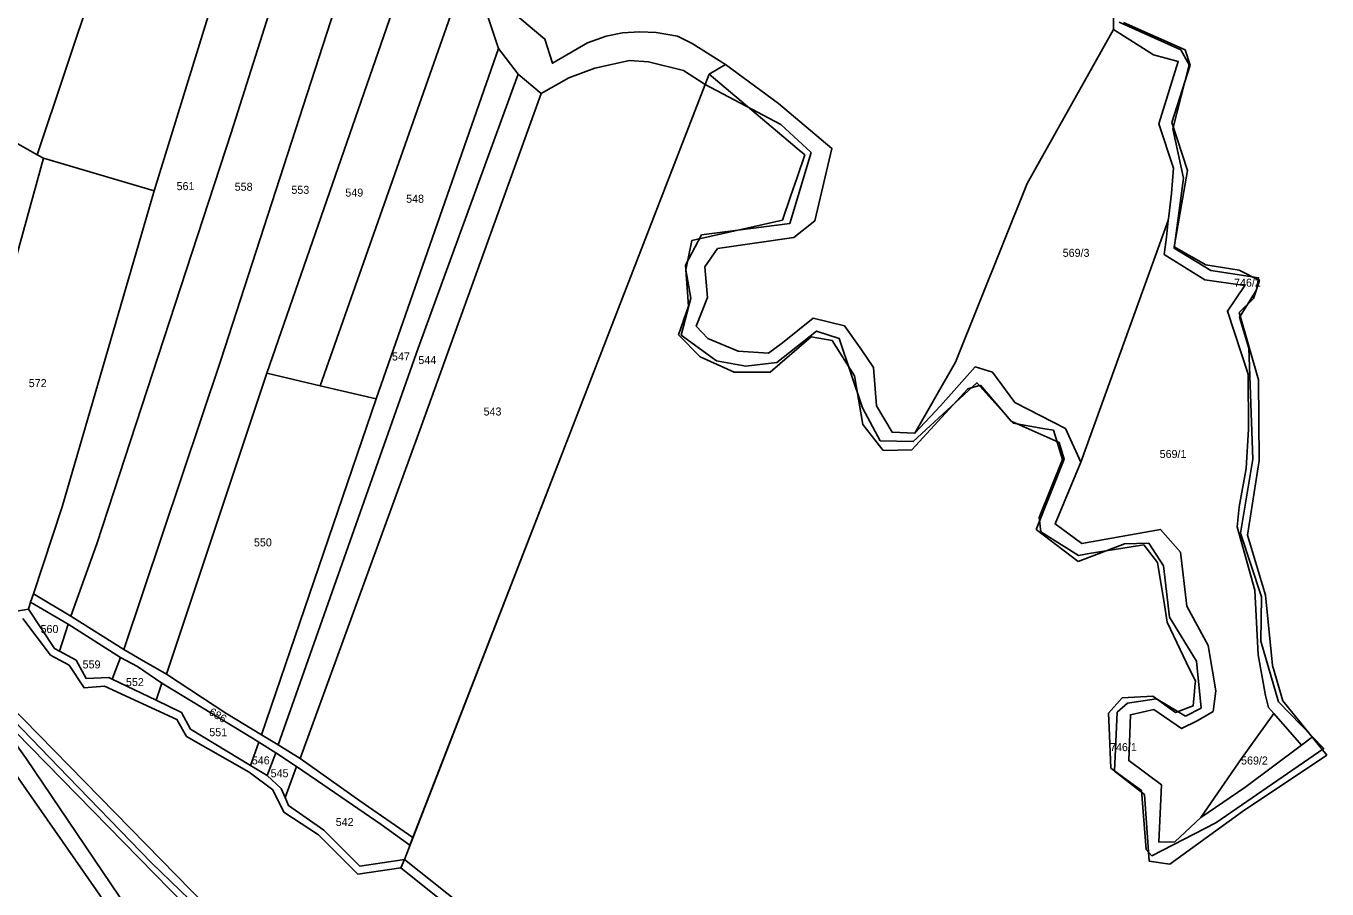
# Model space of a CAD drawing. Extents: x -629983 to -626385, y -1072828 to -1067897.
# Drawn here: x -627583.2 to -627095.5, y -1069313.4 to -1068989.9 of the extents above; entities that cross this region are included whole.
import ezdxf

# ---------------------------------------------------------------- set-up
doc = ezdxf.new("R2010")
doc.units = 0
for name, color, linetype in [('Katastrální hranice', 7, 'Continuous'), ('Parcela nároku', 7, 'Continuous'), ('Parcelní číslo', 7, 'Continuous'), ('Plocha PÚ', 7, 'Continuous'), ('Převzatý obvod_Vraclav', 7, 'Continuous'), ('voda', 7, 'Continuous'), ('Šetřený obvod', 7, 'Continuous')]:
    doc.layers.add(name, color=color, linetype=linetype)

msp = doc.modelspace()

# ---------------------------------------------------------------- linework, layer by layer
at = {"layer": 'Katastrální hranice'}
for p, q in [((-627171.7, -1068988.54), (-627148.6, -1068998.82)), ((-627148.6, -1068998.82), (-627146.76, -1069004.53)), ((-627146.76, -1069004.53), (-627153.59, -1069026.1)), ((-627328.55, -1069011.86), (-627300.22, -1069026.82)), ((-627288.82, -1069037.27), (-627300.22, -1069026.82)), ((-627153.59, -1069026.1), (-627147.78, -1069044.05)), ((-627296.85, -1069063.86), (-627288.82, -1069037.27)), ((-627152.7, -1069072.62), (-627147.78, -1069044.05)), ((-627329.97, -1069068.14), (-627296.85, -1069063.86)), ((-627335.89, -1069079.56), (-627329.97, -1069068.14)), ((-627152.7, -1069072.62), (-627140.88, -1069079.45)), ((-627334.78, -1069094.89), (-627335.89, -1069079.56)), ((-627140.88, -1069079.45), (-627128.35, -1069081.39)), ((-627120.7, -1069085.26), (-627128.35, -1069081.39)), ((-627120.7, -1069085.26), (-627122.95, -1069092.06)), ((-627122.95, -1069092.06), (-627128.35, -1069097.26)), ((-627338.55, -1069105.7), (-627334.78, -1069094.89)), ((-627128.35, -1069097.26), (-627121.12, -1069122.54)), ((-627330.5, -1069113.86), (-627338.55, -1069105.7)), ((-627288.86, -1069106.44), (-627304.24, -1069119.7)), ((-627281.01, -1069107.77), (-627288.86, -1069106.44)), ((-627281.01, -1069107.77), (-627272.57, -1069121)), ((-627317.66, -1069119.67), (-627330.5, -1069113.86)), ((-627304.24, -1069119.7), (-627317.66, -1069119.67)), ((-627269.42, -1069139.31), (-627272.57, -1069121)), ((-627251.09, -1069148.79), (-627230.1, -1069125.95)), ((-627225.31, -1069124.53), (-627230.1, -1069125.95)), ((-627213.79, -1069137.99), (-627225.31, -1069124.53)), ((-627121.12, -1069122.54), (-627120.91, -1069152.77)), ((-627261.88, -1069149), (-627269.42, -1069139.31)), ((-627195.86, -1069146.04), (-627213.79, -1069137.99)), ((-627195.86, -1069146.04), (-627194.03, -1069152.22)), ((-627251.09, -1069148.79), (-627261.88, -1069149)), ((-627204.42, -1069178.63), (-627194.03, -1069152.22)), ((-627120.91, -1069152.77), (-627125.19, -1069180.77)), ((-627188.78, -1069190.62), (-627204.42, -1069178.63)), ((-627125.19, -1069180.77), (-627118.47, -1069203.27)), ((-627188.78, -1069190.62), (-627171.36, -1069183.99)), ((-627162.18, -1069183.69), (-627171.36, -1069183.99)), ((-627156.68, -1069192.25), (-627162.18, -1069183.69)), ((-627154.44, -1069211.52), (-627156.68, -1069192.25)), ((-627118.47, -1069203.27), (-627115.84, -1069229.53)), ((-627144.36, -1069228), (-627154.44, -1069211.52)), ((-627142.63, -1069245.53), (-627144.36, -1069228)), ((-627115.84, -1069229.53), (-627111.96, -1069242.89)), ((-627174.09, -1069247.13), (-627170.22, -1069243.66)), ((-627170.22, -1069243.66), (-627159.31, -1069242.13)), ((-627159.31, -1069242.13), (-627148.51, -1069248.56)), ((-627095.45, -1069263.18), (-627111.96, -1069242.89)), ((-627175.11, -1069269.25), (-627174.09, -1069247.13)), ((-627148.51, -1069248.56), (-627142.63, -1069245.53)), ((-627095.45, -1069263.18), (-627127.11, -1069284.34)), ((-627163.8, -1069277.92), (-627175.11, -1069269.25)), ((-627162.07, -1069302.89), (-627163.8, -1069277.92)), ((-627154.32, -1069304.02), (-627127.11, -1069284.34)), ((-627154.32, -1069304.02), (-627162.07, -1069302.89))]:
    msp.add_line(p, q, dxfattribs=at)
at = {"layer": 'Parcela nároku'}
for points in [[(-627541.67, -1068910.56), (-627536.66, -1068911.49), (-627578.96, -1069038.13), (-627619.33, -1069015.15), (-627605.58, -1068990.76), (-627611.83, -1068980.04), (-627603.02, -1068974.61), (-627603.36, -1068962.42), (-627603.37, -1068948.03), (-627594.26, -1068943.85), (-627593.58, -1068939.95), (-627599.72, -1068932.52), (-627593.42, -1068929.74), (-627589.61, -1068912.68), (-627582.29, -1068903.91), (-627585.58, -1068896.11), (-627570.08, -1068877.27), (-627576.3, -1068868.62), (-627578.92, -1068858.11), (-627561.45, -1068858.96), (-627546.19, -1068860.81), (-627542.18, -1068861.77)], [(-627512.64, -1068894.88), (-627524.24, -1068899.27), (-627531.23, -1068888.31), (-627537.68, -1068862.77), (-627542.18, -1068861.77), (-627541.67, -1068910.56), (-627536.66, -1068911.49), (-627578.96, -1069038.13), (-627576.57, -1069039.46), (-627535.1, -1069051.69), (-627487.33, -1068896.72), (-627481.96, -1068878.87), (-627493.96, -1068868.07), (-627501.98, -1068875.39)], [(-627569.68, -1069170.14), (-627535.1, -1069051.69), (-627487.33, -1068896.72), (-627477.1, -1068901.39), (-627465.34, -1068898.88), (-627464.83, -1068899.07), (-627506.25, -1069029.91), (-627556.61, -1069184.03), (-627566.39, -1069211.09), (-627580.43, -1069202.71)], [(-627556.61, -1069184.03), (-627506.25, -1069029.91), (-627464.83, -1068899.07), (-627443.39, -1068907.08), (-627457.17, -1068951.58), (-627510.15, -1069115.2), (-627546.54, -1069223.62), (-627566.39, -1069211.09)], [(-627510.15, -1069115.2), (-627546.54, -1069223.62), (-627539.83, -1069227.42), (-627530.47, -1069232.83), (-627492.9, -1069120.08), (-627436.21, -1068956.4), (-627421.11, -1068910.74), (-627443.39, -1068907.08), (-627457.17, -1068951.58)], [(-627412.16, -1068949.45), (-627421.11, -1068910.74), (-627436.21, -1068956.4), (-627492.9, -1069120.08), (-627472.93, -1069124.75), (-627424.1, -1068986.06)], [(-627424.1, -1068986.06), (-627472.93, -1069124.75), (-627451.96, -1069129.61), (-627406.09, -1068998.31), (-627410.09, -1068986.34), (-627396.68, -1068958.95), (-627412.16, -1068949.45)], [(-627153.03, -1069043.12), (-627158.45, -1069026.6), (-627151.2, -1069003.24), (-627160.54, -1069000.75), (-627175.43, -1068991.27), (-627207.81, -1069048.87), (-627234.74, -1069115.92), (-627249.99, -1069142.48), (-627240.29, -1069132.24), (-627227.4, -1069117.68), (-627220.84, -1069119.62), (-627212.42, -1069130.99), (-627193.5, -1069140.77), (-627187.75, -1069153.41), (-627154.98, -1069062.85), (-627154.79, -1069061.15), (-627153.73, -1069052.7)], [(-627398.73, -1069007.96), (-627406.09, -1068998.31), (-627451.96, -1069129.61), (-627494.94, -1069255.52), (-627488.59, -1069259.39), (-627436.19, -1069110.62)], [(-627390.07, -1069015.16), (-627435.04, -1069140.01), (-627480.41, -1069264.43), (-627458.05, -1069280.3), (-627438.14, -1069294.1), (-627382.86, -1069151.75), (-627328.55, -1069011.86), (-627336.66, -1069006.57), (-627349.81, -1069003.35), (-627356.88, -1069002.81), (-627369.99, -1069005.68), (-627379.69, -1069009.35)], [(-627227.4, -1069117.68), (-627220.84, -1069119.62), (-627212.42, -1069130.99), (-627193.5, -1069140.77), (-627187.75, -1069153.41), (-627197.41, -1069176.54), (-627187.4, -1069183.85), (-627157.84, -1069178.59), (-627150.38, -1069187.1), (-627148.02, -1069207.37), (-627140.05, -1069222.07), (-627137.14, -1069239.05), (-627138.16, -1069246.78), (-627144.09, -1069250.38), (-627149.96, -1069253.25), (-627160.35, -1069246.06), (-627169.11, -1069248.06), (-627169.79, -1069265.22), (-627157.54, -1069274.32), (-627158.44, -1069295.77), (-627152.52, -1069295.72), (-627142.8, -1069286.62), (-627126.24, -1069275.36), (-627105, -1069259.45), (-627100.87, -1069256.36), (-627096.67, -1069260.71), (-627137.18, -1069288.52), (-627161.06, -1069300.91), (-627163.18, -1069298.5), (-627164.99, -1069276.5), (-627170.3, -1069272.59), (-627176.48, -1069268.04), (-627177.15, -1069252.81), (-627177.39, -1069247.48), (-627172.25, -1069241.74), (-627160.76, -1069241.13), (-627152.29, -1069247.18), (-627145.64, -1069244.76), (-627145.11, -1069239.36), (-627144.93, -1069237.46), (-627144.74, -1069235.46), (-627148.06, -1069228.53), (-627155.32, -1069213.39), (-627156.4, -1069206.82), (-627158.94, -1069191.02), (-627164.08, -1069184.37), (-627184.58, -1069187.66), (-627188.57, -1069188.3), (-627202.78, -1069179.54), (-627203.38, -1069174.09), (-627194.62, -1069152.33), (-627197.94, -1069141.44), (-627201.92, -1069140.72), (-627213.06, -1069138.72), (-627226.66, -1069123.61), (-627250.55, -1069145.68), (-627262.94, -1069145.37), (-627269.59, -1069132.98), (-627278.36, -1069106.98), (-627286.82, -1069104.26), (-627301.64, -1069116.05), (-627313.3, -1069117.41), (-627324.31, -1069115.44), (-627337.61, -1069105.77), (-627333.98, -1069091.86), (-627335.8, -1069081.29), (-627333.51, -1069070.24), (-627299.6, -1069062.62), (-627296.56, -1069053.77), (-627294, -1069046.34), (-627291.22, -1069038.24), (-627294.04, -1069035.85), (-627297.45, -1069032.97), (-627327.03, -1069007.95), (-627320.9, -1069004.32), (-627301.05, -1069018.97), (-627281.06, -1069035.81), (-627287.49, -1069062.94), (-627295.37, -1069069.14), (-627323.93, -1069073.27), (-627328.73, -1069080.17), (-627327.73, -1069091.72), (-627331.92, -1069102.35), (-627327.55, -1069107.01), (-627316.25, -1069111.77), (-627304.84, -1069112.56), (-627299.63, -1069108.67), (-627288.12, -1069099.37), (-627276.3, -1069102.3), (-627270.45, -1069110.54), (-627265.48, -1069117.92), (-627264.36, -1069132.27), (-627258.48, -1069142.1), (-627249.99, -1069142.48), (-627240.29, -1069132.24)], [(-627390.07, -1069015.16), (-627398.73, -1069007.96), (-627436.19, -1069110.62), (-627488.59, -1069259.39), (-627480.41, -1069264.43), (-627435.04, -1069140.01)], [(-627630.68, -1069046.56), (-627633.57, -1069076.26), (-627640.03, -1069086.3), (-627640.24, -1069104.24), (-627647.79, -1069115.17), (-627646.65, -1069141.16), (-627654.96, -1069145.76), (-627657.96, -1069171.17), (-627635.13, -1069183.43), (-627626.6, -1069183.39), (-627618.88, -1069190.06), (-627601.99, -1069131.19), (-627576.57, -1069039.46), (-627578.96, -1069038.13), (-627619.33, -1069015.15), (-627620.79, -1069017.75), (-627620.11, -1069035.1)], [(-627576.57, -1069039.46), (-627601.99, -1069131.19), (-627618.88, -1069190.06), (-627595.18, -1069210.65), (-627582.28, -1069208.53), (-627581.46, -1069205.86), (-627580.43, -1069202.71), (-627569.68, -1069170.14), (-627535.1, -1069051.69)], [(-627149.96, -1069253.25), (-627160.35, -1069246.06), (-627169.11, -1069248.06), (-627169.79, -1069265.22), (-627157.54, -1069274.32), (-627158.44, -1069295.77), (-627152.52, -1069295.72), (-627142.8, -1069286.62), (-627127.55, -1069264.47), (-627115.37, -1069247.62), (-627117.37, -1069245.34), (-627118.47, -1069240.89), (-627121.29, -1069225.63), (-627122.49, -1069201.41), (-627129.11, -1069177.56), (-627128.32, -1069170.17), (-627125.72, -1069155.7), (-627124.92, -1069140.99), (-627124.99, -1069120.42), (-627132.76, -1069096.82), (-627126.21, -1069087.14), (-627141.24, -1069085.01), (-627156.5, -1069075.53), (-627155.66, -1069069.03), (-627154.98, -1069062.85), (-627187.75, -1069153.41), (-627197.41, -1069176.54), (-627187.4, -1069183.85), (-627157.84, -1069178.59), (-627150.38, -1069187.1), (-627148.02, -1069207.37), (-627140.05, -1069222.07), (-627137.14, -1069239.05), (-627138.16, -1069246.78), (-627144.09, -1069250.38)], [(-627530.47, -1069232.83), (-627492.9, -1069120.08), (-627472.93, -1069124.75), (-627451.96, -1069129.61), (-627494.94, -1069255.52), (-627508.21, -1069247.44)], [(-627580.43, -1069202.71), (-627566.39, -1069211.09), (-627546.54, -1069223.62), (-627539.83, -1069227.42), (-627530.47, -1069232.83), (-627508.21, -1069247.44), (-627494.94, -1069255.52), (-627488.59, -1069259.39), (-627480.41, -1069264.43), (-627458.05, -1069280.3), (-627438.14, -1069294.1), (-627439.23, -1069296.91), (-627450, -1069289.16), (-627469.49, -1069275.78), (-627481.76, -1069267.41), (-627489.58, -1069262.38), (-627495.87, -1069258.33), (-627498.28, -1069256.78), (-627532.3, -1069236.24), (-627541.41, -1069230.01), (-627547.74, -1069226.61), (-627567.33, -1069214.14), (-627581.46, -1069205.86)], [(-627567.33, -1069214.14), (-627581.46, -1069205.86), (-627582.28, -1069208.53), (-627572.48, -1069223.26), (-627570.64, -1069224.23)], [(-627324.81, -1069488.6), (-627339.13, -1069480.44), (-627379.75, -1069454.55), (-627515.4, -1069319.93), (-627618.57, -1069214.56), (-627598.81, -1069242.61), (-627517.7, -1069325.48), (-627383, -1069459.06), (-627347.15, -1069482.18), (-627343.99, -1069484.22), (-627337.43, -1069488.19), (-627332.48, -1069490.93)], [(-627547.74, -1069226.61), (-627567.33, -1069214.14), (-627570.64, -1069224.23), (-627564.38, -1069227.55), (-627560.57, -1069234.49), (-627552.09, -1069234.07), (-627550.84, -1069234.68)], [(-627583.15, -1069264.51), (-627598.81, -1069242.61), (-627622.78, -1069217.95), (-627587.87, -1069269.14), (-627556.92, -1069313.71), (-627469.62, -1069440.57), (-627454.33, -1069455.51), (-627442.87, -1069461.88), (-627440.52, -1069456.67), (-627453.31, -1069449.31), (-627463.77, -1069438.44), (-627548.25, -1069316.09)], [(-627532.3, -1069236.24), (-627541.41, -1069230.01), (-627547.74, -1069226.61), (-627550.84, -1069234.68), (-627534.41, -1069242.63)], [(-627532.3, -1069236.24), (-627534.41, -1069242.63), (-627524.93, -1069247.22), (-627521.49, -1069253.4), (-627499, -1069267.02), (-627495.87, -1069258.33), (-627498.28, -1069256.78)], [(-627517.7, -1069325.48), (-627598.81, -1069242.61), (-627583.15, -1069264.51), (-627548.25, -1069316.09), (-627463.77, -1069438.44), (-627453.31, -1069449.31), (-627440.52, -1069456.67), (-627413.75, -1069471.16), (-627367.69, -1069489.87), (-627345.93, -1069493.32), (-627347.15, -1069482.18), (-627383, -1069459.06)], [(-627105, -1069259.45), (-627115.37, -1069247.62), (-627127.55, -1069264.47), (-627142.8, -1069286.62), (-627126.24, -1069275.36)], [(-627489.58, -1069262.38), (-627495.87, -1069258.33), (-627499, -1069267.02), (-627492.83, -1069270.76)], [(-627481.76, -1069267.41), (-627489.58, -1069262.38), (-627492.83, -1069270.76), (-627487.54, -1069275.75), (-627486.07, -1069279.11)], [(-627450, -1069289.16), (-627469.49, -1069275.78), (-627481.76, -1069267.41), (-627486.07, -1069279.11), (-627484.75, -1069282.12), (-627471.52, -1069291.37), (-627457.98, -1069304.83), (-627441.31, -1069302.27), (-627439.56, -1069297.78), (-627439.23, -1069296.91)], [(-627556.92, -1069313.71), (-627587.87, -1069269.14), (-627630.67, -1069367.65), (-627602.8, -1069390.7), (-627584.07, -1069415.57), (-627532.45, -1069447.67), (-627450.43, -1069478.79), (-627442.87, -1069461.88), (-627454.33, -1069455.51), (-627469.62, -1069440.57)]]:
    msp.add_lwpolyline(points, close=True, dxfattribs=at)
for points in [[(-627400.42, -1068984.9), (-627388.67, -1068994.83), (-627385.83, -1069003.83), (-627372.64, -1068996.2), (-627365.65, -1068993.72), (-627359.51, -1068992.45), (-627353.12, -1068992.07), (-627346.96, -1068992.36), (-627338.89, -1068993.71), (-627333.4, -1068996.51), (-627320.9, -1069004.32), (-627301.05, -1069018.97), (-627281.06, -1069035.81), (-627287.49, -1069062.94), (-627295.37, -1069069.14), (-627323.93, -1069073.27), (-627328.73, -1069080.17), (-627327.73, -1069091.72), (-627331.92, -1069102.35), (-627327.55, -1069107.01), (-627316.25, -1069111.77), (-627304.84, -1069112.56), (-627299.63, -1069108.67), (-627288.12, -1069099.37), (-627276.3, -1069102.3), (-627270.45, -1069110.54), (-627265.48, -1069117.92), (-627264.36, -1069132.27), (-627258.48, -1069142.1), (-627249.99, -1069142.48), (-627234.74, -1069115.92), (-627207.81, -1069048.87), (-627175.43, -1068991.27), (-627175.34, -1068967.31)], [(-627173.36, -1068988.43), (-627150.27, -1068998.85), (-627147.07, -1069004.51), (-627153.26, -1069028.47), (-627149.29, -1069046.9), (-627152.72, -1069073.19), (-627139, -1069081.58), (-627122.61, -1069084.02), (-627121.1, -1069084.24), (-627121.86, -1069088.82), (-627124.01, -1069092.27), (-627128.22, -1069099.03), (-627124.72, -1069110.61), (-627123.27, -1069152.25), (-627127.81, -1069179.99), (-627119.95, -1069203.87), (-627120.25, -1069220.5), (-627113.6, -1069243.17), (-627100.87, -1069256.36), (-627105, -1069259.45), (-627115.37, -1069247.62), (-627117.37, -1069245.34), (-627118.47, -1069240.89), (-627121.29, -1069225.63), (-627122.49, -1069201.41), (-627129.11, -1069177.56), (-627128.32, -1069170.17), (-627125.72, -1069155.7), (-627124.92, -1069140.99), (-627124.99, -1069120.42), (-627132.76, -1069096.82), (-627126.21, -1069087.14), (-627141.24, -1069085.01), (-627156.5, -1069075.53), (-627155.66, -1069069.03), (-627154.98, -1069062.85), (-627154.79, -1069061.15), (-627153.73, -1069052.7), (-627153.03, -1069043.12), (-627158.45, -1069026.6), (-627151.2, -1069003.24), (-627160.54, -1069000.75), (-627175.43, -1068991.27), (-627175.34, -1068967.31)], [(-627400.42, -1068984.9), (-627388.67, -1068994.83), (-627385.83, -1069003.83), (-627372.64, -1068996.2), (-627365.65, -1068993.72), (-627359.51, -1068992.45), (-627353.12, -1068992.07), (-627346.96, -1068992.36), (-627338.89, -1068993.71), (-627333.4, -1068996.51), (-627320.9, -1069004.32), (-627327.03, -1069007.95), (-627328.55, -1069011.86), (-627336.66, -1069006.57), (-627349.81, -1069003.35), (-627356.88, -1069002.81), (-627369.99, -1069005.68), (-627379.69, -1069009.35), (-627390.07, -1069015.16), (-627398.73, -1069007.96), (-627406.09, -1068998.31), (-627410.09, -1068986.34)], [(-627595.18, -1069210.65), (-627582.28, -1069208.53), (-627572.48, -1069223.26), (-627570.64, -1069224.23), (-627564.38, -1069227.55), (-627560.57, -1069234.49), (-627552.09, -1069234.07), (-627550.84, -1069234.68), (-627534.41, -1069242.63), (-627524.93, -1069247.22), (-627521.49, -1069253.4), (-627499, -1069267.02), (-627492.83, -1069270.76), (-627487.54, -1069275.75), (-627486.07, -1069279.11), (-627484.75, -1069282.12), (-627471.52, -1069291.37), (-627457.98, -1069304.83), (-627441.31, -1069302.27), (-627442.61, -1069305.38), (-627458.72, -1069307.75), (-627473.54, -1069293.1), (-627486.53, -1069284.58), (-627490.6, -1069276.16), (-627499.48, -1069269.57), (-627523, -1069256.2), (-627526.6, -1069249.89), (-627553.8, -1069237.39), (-627561.34, -1069238.01), (-627566.94, -1069229.48), (-627573.99, -1069225.75), (-627584.33, -1069212.03)], [(-627618.57, -1069214.56), (-627515.4, -1069319.93)], [(-627401.66, -1069338.27), (-627442.61, -1069305.38), (-627458.72, -1069307.75), (-627473.54, -1069293.1), (-627486.53, -1069284.58), (-627490.6, -1069276.16), (-627499.48, -1069269.57), (-627523, -1069256.2), (-627526.6, -1069249.89), (-627553.8, -1069237.39), (-627561.34, -1069238.01), (-627566.94, -1069229.48), (-627573.99, -1069225.75), (-627584.33, -1069212.03)], [(-627401.66, -1069338.27), (-627442.61, -1069305.38), (-627441.31, -1069302.27), (-627394.24, -1069339.61)]]:
    msp.add_lwpolyline(points, dxfattribs=at)
at = {"layer": 'Plocha PÚ'}
for points in [[(-627328.55, -1069011.86), (-627336.66, -1069006.57), (-627349.81, -1069003.35), (-627356.88, -1069002.81), (-627369.99, -1069005.68), (-627379.69, -1069009.35), (-627390.07, -1069015.16), (-627398.73, -1069007.96), (-627406.09, -1068998.31), (-627410.09, -1068986.34)], [(-627394.24, -1069339.61), (-627441.31, -1069302.27), (-627439.56, -1069297.78), (-627439.23, -1069296.91), (-627438.14, -1069294.1), (-627382.86, -1069151.75), (-627328.55, -1069011.86)]]:
    msp.add_lwpolyline(points, dxfattribs=at)
at = {"layer": 'Převzatý obvod_Vraclav'}
for points in [[(-627328.55, -1069011.86), (-627382.86, -1069151.75), (-627439.56, -1069297.78)], [(-627439.56, -1069297.78), (-627441.31, -1069302.27), (-627394.24, -1069339.61)]]:
    msp.add_lwpolyline(points, dxfattribs=at)
at = {"layer": 'voda'}
msp.add_lwpolyline([(-627608.69, -1069228.58), (-627567.33, -1069271.37), (-627536.18, -1069303.59), (-627504.31, -1069334.27), (-627485.76, -1069353.94), (-627464.97, -1069374.06), (-627447.22, -1069392.83), (-627416.71, -1069421.47), (-627386.71, -1069452.38), (-627377.38, -1069459.57), (-627356.25, -1069473.06), (-627328.64, -1069489.76), (-627308.58, -1069501.31), (-627278, -1069518.91), (-627267.24, -1069526.16), (-627251.07, -1069535.67), (-627238.49, -1069545.79), (-627221.22, -1069559.68), (-627209.33, -1069569.24), (-627201.32, -1069574.3)], dxfattribs=at)
at = {"layer": 'Šetřený obvod'}
for p, q in [((-627410.09, -1068986.34), (-627406.09, -1068998.31)), ((-627406.09, -1068998.31), (-627398.73, -1069007.96)), ((-627369.99, -1069005.68), (-627356.88, -1069002.81)), ((-627356.88, -1069002.81), (-627349.81, -1069003.35)), ((-627349.81, -1069003.35), (-627336.66, -1069006.57)), ((-627398.73, -1069007.96), (-627390.07, -1069015.16)), ((-627390.07, -1069015.16), (-627379.69, -1069009.35)), ((-627379.69, -1069009.35), (-627369.99, -1069005.68)), ((-627336.66, -1069006.57), (-627328.55, -1069011.86))]:
    msp.add_line(p, q, dxfattribs=at)

# ---------------------------------------------------------------- texts
at = {"layer": 'Parcelní číslo'}
for s, p in [('561', (-627526.72, -1069051.42)), ('558', (-627504.94, -1069051.65)), ('553', (-627483.68, -1069052.8)), ('549', (-627463.46, -1069053.84)), ('548', (-627440.67, -1069056.15)), ('569/3', (-627194.53, -1069076.41)), ('746/2', (-627130.29, -1069087.61)), ('547', (-627445.97, -1069115.27)), ('544', (-627436.09, -1069116.62)), ('572', (-627582.15, -1069125.25)), ('543', (-627411.64, -1069135.89)), ('569/1', (-627158.18, -1069151.81)), ('550', (-627497.72, -1069184.95)), ('560', (-627577.73, -1069217.43)), ('559', (-627561.95, -1069230.68)), ('552', (-627545.7, -1069237.29)), ('551', (-627514.47, -1069256.09)), ('746/1', (-627176.79, -1069261.7)), ('546', (-627498.52, -1069266.65)), ('569/2', (-627127.65, -1069266.7)), ('545', (-627491.47, -1069271.48)), ('542', (-627467.07, -1069289.75))]:
    msp.add_text(s, height=3, dxfattribs=at).set_placement(p)
msp.add_text('686', height=3, rotation=329.2097, dxfattribs=at).set_placement((-627514.91, -1069247.81))

doc.saveas('drawing.dxf')
